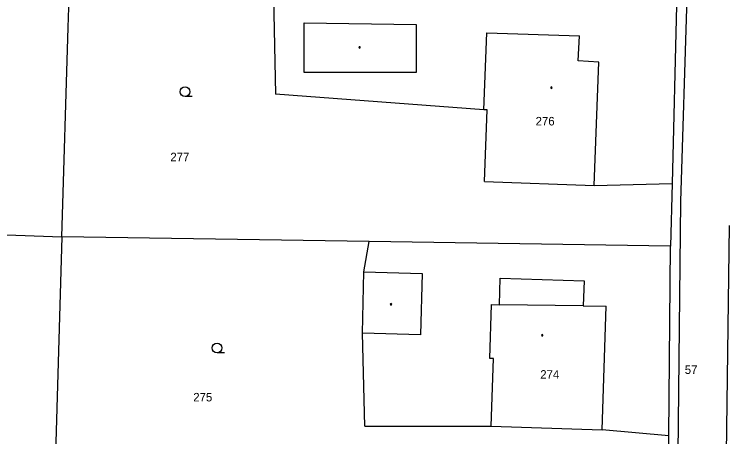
# Model space of a CAD drawing. Extents: x -454285 to -453563, y -1108687 to -1108249.
# Drawn here: x -453927.9 to -453869.2, y -1108561.2 to -1108526.5 of the extents above; entities that cross this region are included whole.
import ezdxf

# ---------------------------------------------------------------- set-up
doc = ezdxf.new("R2010")
doc.units = 0
for name, color, linetype in [('1', 7, 'Continuous'), ('14', 7, 'Continuous'), ('15', 7, 'Continuous'), ('16', 7, 'Continuous'), ('2', 7, 'Continuous'), ('23', 7, 'Continuous'), ('25', 7, 'Continuous')]:
    doc.layers.add(name, color=color, linetype=linetype)

# ---------------------------------------------------------------- blocks, each defined once
blk = doc.blocks.new('Z402')
for start, end in [(0, 180), (180, 0)]:
    blk.add_arc((0, 0), 0.15, start, end)
blk = doc.blocks.new('Z3040')
blk.add_line((1.5, 0), (0, 0))
blk.add_circle((0, 1), 1)

msp = doc.modelspace()

# ---------------------------------------------------------------- linework, layer by layer
at = {"layer": '1'}
for p, q in [((-453923.427, -1108527.581), (-453923.337, -1108524.721)), ((-453906.577, -1108524.851), (-453906.417, -1108533.071)), ((-453873.507, -1108525.781), (-453873.857, -1108540.391)), ((-453923.957, -1108544.791), (-453923.427, -1108527.581)), ((-453889.297, -1108534.351), (-453906.417, -1108533.071)), ((-453889.047, -1108534.361), (-453889.297, -1108534.351)), ((-453889.257, -1108540.241), (-453889.047, -1108534.361)), ((-453889.257, -1108540.241), (-453880.247, -1108540.561)), ((-453880.247, -1108540.561), (-453873.857, -1108540.391)), ((-453873.857, -1108540.391), (-453873.977, -1108545.541)), ((-453948.847, -1108543.851), (-453923.957, -1108544.791)), ((-453923.957, -1108544.791), (-453924.537, -1108564.601)), ((-453898.727, -1108545.171), (-453923.957, -1108544.791)), ((-453899.157, -1108547.651), (-453898.727, -1108545.171)), ((-453873.977, -1108545.541), (-453898.727, -1108545.171)), ((-453874.117, -1108561.141), (-453873.977, -1108545.541)), ((-453899.267, -1108552.691), (-453899.157, -1108547.651)), ((-453899.087, -1108560.331), (-453899.267, -1108552.691)), ((-453899.087, -1108560.331), (-453888.717, -1108560.331)), ((-453888.717, -1108560.331), (-453879.597, -1108560.631)), ((-453874.117, -1108561.141), (-453879.597, -1108560.631)), ((-453874.157, -1108565.631), (-453874.117, -1108561.141))]:
    msp.add_line(p, q, dxfattribs=at)
at = {"layer": '2'}
for p, q in [((-453871.397, -1108484.241), (-453873.167, -1108541.891)), ((-453904.067, -1108531.291), (-453904.057, -1108527.211)), ((-453904.057, -1108527.211), (-453894.857, -1108527.331)), ((-453894.857, -1108527.331), (-453894.857, -1108531.291)), ((-453889.297, -1108534.351), (-453889.067, -1108528.011)), ((-453889.067, -1108528.011), (-453881.447, -1108528.281)), ((-453881.577, -1108530.331), (-453881.447, -1108528.281)), ((-453879.877, -1108530.441), (-453881.577, -1108530.331)), ((-453880.247, -1108540.561), (-453879.877, -1108530.441)), ((-453894.857, -1108531.291), (-453904.067, -1108531.291)), ((-453873.167, -1108541.891), (-453873.607, -1108582.221)), ((-453869.727, -1108586.751), (-453869.147, -1108543.861)), ((-453899.157, -1108547.651), (-453894.367, -1108547.791)), ((-453894.367, -1108547.791), (-453894.507, -1108552.831)), ((-453888.027, -1108550.361), (-453887.957, -1108548.191)), ((-453887.957, -1108548.191), (-453881.077, -1108548.411)), ((-453881.077, -1108548.411), (-453881.147, -1108550.461)), ((-453888.827, -1108554.771), (-453888.687, -1108550.341)), ((-453888.687, -1108550.341), (-453888.027, -1108550.361)), ((-453881.147, -1108550.461), (-453888.027, -1108550.361)), ((-453881.147, -1108550.461), (-453879.267, -1108550.491)), ((-453879.597, -1108560.631), (-453879.267, -1108550.491)), ((-453894.507, -1108552.831), (-453899.267, -1108552.691)), ((-453888.527, -1108554.781), (-453888.827, -1108554.771)), ((-453888.717, -1108560.331), (-453888.527, -1108554.781))]:
    msp.add_line(p, q, dxfattribs=at)

# ---------------------------------------------------------------- block references
at = {"layer": '23', "xscale": 0.4, "yscale": 0.4000000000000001}
for p in [(-453913.837, -1108533.261), (-453911.207, -1108554.311)]:
    msp.add_blockref('Z3040', p, dxfattribs=at)
at = {"layer": '25', "xscale": 0.4, "yscale": 0.4000000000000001}
for p in [(-453899.507, -1108529.221), (-453883.757, -1108532.531), (-453896.927, -1108550.321), (-453884.517, -1108552.871)]:
    msp.add_blockref('Z402', p, dxfattribs=at)

# ---------------------------------------------------------------- texts
at = {"layer": '14'}
for s, p in [('277', (-453915.04, -1108538.571)), ('275', (-453913.16, -1108558.311))]:
    msp.add_text(s, height=0.7, dxfattribs=at).set_placement(p)
at = {"layer": '15'}
for s, p in [('276', (-453885.06, -1108535.631)), ('274', (-453884.68, -1108556.441))]:
    msp.add_text(s, height=0.7, dxfattribs=at).set_placement(p)
at = {"layer": '16'}
msp.add_text('57', height=0.7, dxfattribs=at).set_placement((-453872.817, -1108556.051))

doc.saveas('drawing.dxf')
